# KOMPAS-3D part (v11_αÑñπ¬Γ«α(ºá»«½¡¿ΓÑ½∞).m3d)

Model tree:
1. Эскиз:1
2. Операция выдавливания:1
     Расстояние 1 = 141; Расстояние 2 = 141
3. Эскиз:2
4. Операция выдавливания:2
     Расстояние 1 = 54; Расстояние 2 = 141
5. Скругление:1
     Радиус = 0.4
6. Эскиз:3
7. Вырезать элемент выдавливания:1
     Расстояние 1 = 25.3
8. Эскиз:4
9. Вырезать элемент выдавливания:2
     Расстояние 1 = 14.4282
10. Эскиз:5
11. Вырезать элемент выдавливания:3
     Расстояние 1 = 20
12. Скругление:3
     Радиус = 1
13. Эскиз:6
14. Вырезать элемент выдавливания:4
     Расстояние 1 = 11.75

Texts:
  Линия-выноска #1
  Линия-выноска #2
  Линия-выноска #3
  Отклонения формы и база
  Марка координационной оси
  Марка/позиционное обозначение с линией-выноской
  Марка/позиционное обозначение на линии
  Марка/позиционное обозначение без линии-выноски
  Текст на чертеже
